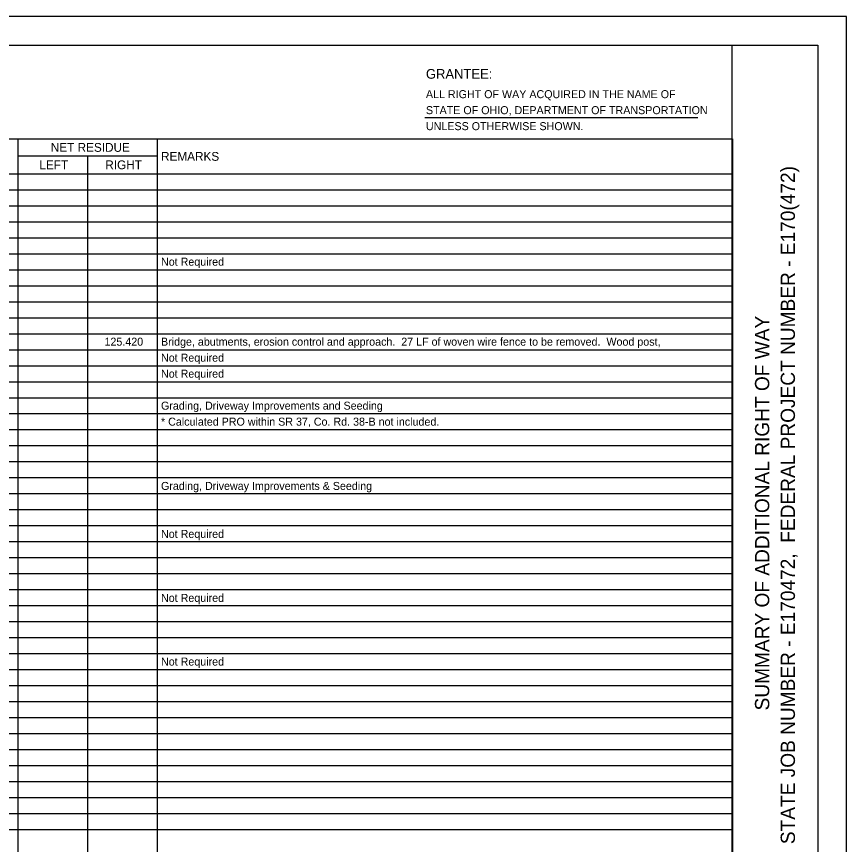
# Model space of a CAD drawing. Extents: x 0 to 34, y -1.2 to 22.
# Drawn here: x 19.48 to 34, y 7.51 to 22 of the extents above; entities that cross this region are included whole.
import ezdxf

# ---------------------------------------------------------------- set-up
doc = ezdxf.new("R2010")
doc.units = 0
for name, color, linetype in [('SH_Border', 7, 'Continuous'), ('SH_Cut_Line', 7, 'Continuous'), ('SH_Data', 7, 'Continuous'), ('SH_Text', 7, 'Continuous')]:
    doc.layers.add(name, color=color, linetype=linetype)

msp = doc.modelspace()

# ---------------------------------------------------------------- linework, layer by layer
at = {"layer": 'SH_Border'}
msp.add_line((32, 0.5), (32, 21.5), dxfattribs=at)
msp.add_lwpolyline([(1.5, 21.5), (33.5, 21.5), (33.5, 0.5), (1.5, 0.5)], close=True, dxfattribs=at)
at = {"layer": 'SH_Cut_Line'}
msp.add_lwpolyline([(0, 0), (34, 0), (34, 22), (0, 22)], close=True, dxfattribs=at)
at = {"layer": 'SH_Text'}
for p, q in [((26.621, 20.235), (31.401, 20.235)), ((1.5, 19.858), (32.004, 19.858)), ((19.502, 19.858), (19.502, 4.409)), ((21.94, 19.858), (21.94, 4.409)), ((32.004, 19.858), (32.004, 4.409)), ((19.502, 19.561), (21.94, 19.561)), ((20.721, 19.561), (20.721, 4.409)), ((1.5, 19.249), (32.004, 19.249)), ((1.5, 18.969), (32.004, 18.969)), ((1.5, 18.689), (32.004, 18.689)), ((1.5, 18.409), (32.004, 18.409)), ((1.5, 18.129), (32.004, 18.129)), ((1.5, 17.849), (32.004, 17.849)), ((1.5, 17.569), (32.004, 17.569)), ((1.5, 17.289), (32.004, 17.289)), ((1.5, 17.009), (32.004, 17.009)), ((1.5, 16.729), (32.004, 16.729)), ((1.5, 16.449), (32.004, 16.449)), ((1.5, 16.169), (32.004, 16.169)), ((1.5, 15.889), (32.004, 15.889)), ((1.5, 15.609), (32.004, 15.609)), ((1.5, 15.329), (32.004, 15.329)), ((1.5, 15.049), (32.004, 15.049)), ((1.5, 14.769), (32.004, 14.769)), ((1.5, 14.489), (32.004, 14.489)), ((1.5, 14.209), (32.004, 14.209)), ((1.5, 13.929), (32.004, 13.929)), ((1.5, 13.649), (32.004, 13.649)), ((1.5, 13.369), (32.004, 13.369)), ((1.5, 13.089), (32.004, 13.089)), ((1.5, 12.809), (32.004, 12.809)), ((1.5, 12.529), (32.004, 12.529)), ((1.5, 12.249), (32.004, 12.249)), ((1.5, 11.969), (32.004, 11.969)), ((1.5, 11.689), (32.004, 11.689)), ((1.5, 11.409), (32.004, 11.409)), ((1.5, 11.129), (32.004, 11.129)), ((1.5, 10.849), (32.004, 10.849)), ((1.5, 10.569), (32.004, 10.569)), ((1.5, 10.289), (32.004, 10.289)), ((1.5, 10.009), (32.004, 10.009)), ((1.5, 9.729), (32.004, 9.729)), ((1.5, 9.449), (32.004, 9.449)), ((1.5, 9.169), (32.004, 9.169)), ((1.5, 8.889), (32.004, 8.889)), ((1.5, 8.609), (32.004, 8.609)), ((1.5, 8.329), (32.004, 8.329)), ((1.5, 8.049), (32.004, 8.049)), ((1.5, 7.769), (32.004, 7.769))]:
    msp.add_line(p, q, dxfattribs=at)

# ---------------------------------------------------------------- texts
at = {"layer": 'SH_Data'}
for s, p in [('STATE JOB NUMBER - E170472,  FEDERAL PROJECT NUMBER - E170(472)', (33.1, 7.513)), ('SUMMARY OF ADDITIONAL RIGHT OF WAY', (32.65, 9.854))]:
    msp.add_text(s, height=0.25, rotation=90, dxfattribs=at).set_placement(p)
at = {"layer": 'SH_Text'}
for s, height, p in [('GRANTEE:', 0.17, (26.642, 20.912)), ('ALL RIGHT OF WAY ACQUIRED IN THE NAME OF', 0.14, (26.642, 20.572)), ('STATE OF OHIO, DEPARTMENT OF TRANSPORTATION', 0.14, (26.642, 20.292)), ('UNLESS OTHERWISE SHOWN.', 0.14, (26.642, 20.012)), ('NET RESIDUE', 0.154, (20.077, 19.633)), ('REMARKS', 0.154, (22.006, 19.476)), ('LEFT', 0.154, (19.877, 19.328)), ('RIGHT', 0.154, (21.031, 19.328)), ('Not Required', 0.14, (22.006, 17.639)), ('125.420', 0.14, (21.017, 16.239)), ('Bridge, abutments, erosion control and approach.  27 LF of woven wire fence to be removed.  Wood post,', 0.14, (22.006, 16.239)), ('Not Required', 0.14, (22.006, 15.959)), ('Not Required', 0.14, (22.006, 15.679)), ('Grading, Driveway Improvements and Seeding', 0.14, (22.006, 15.119)), ('* Calculated PRO within SR 37, Co. Rd. 38-B not included.', 0.14, (22.006, 14.839)), ('Grading, Driveway Improvements & Seeding', 0.14, (22.006, 13.714)), ('Not Required', 0.14, (22.006, 12.874)), ('Not Required', 0.14, (22.006, 11.754)), ('Not Required', 0.14, (22.006, 10.639))]:
    msp.add_text(s, height=height, dxfattribs=at).set_placement(p)

doc.saveas('drawing.dxf')
